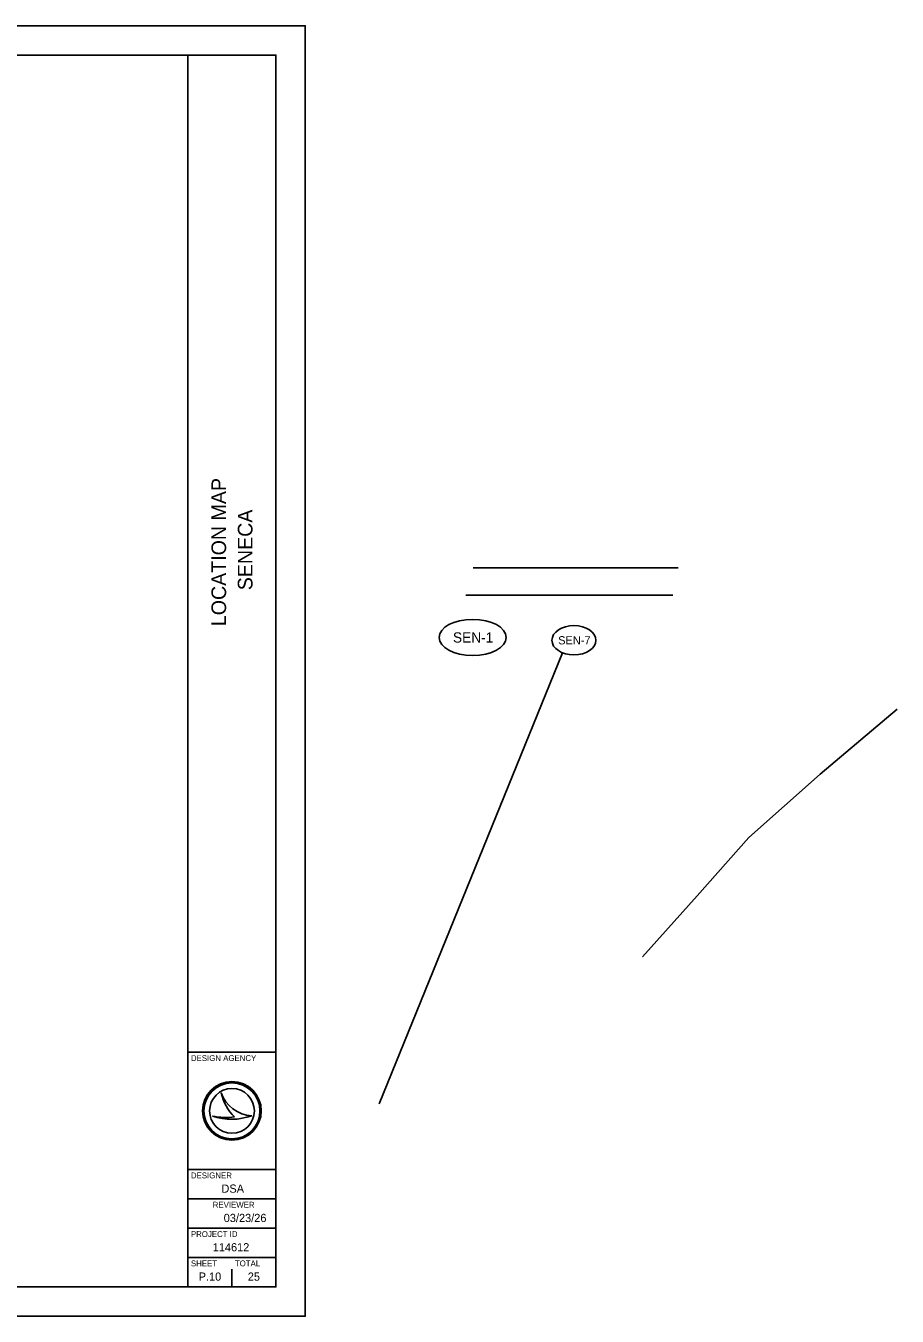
# Model space of a CAD drawing. Extents: x 0 to 882, y 0 to 440.
# Drawn here: x 584.7 to 881.9, y 0 to 440 of the extents above; entities that cross this region are included whole.
import ezdxf

# ---------------------------------------------------------------- set-up
doc = ezdxf.new("R2010")
doc.units = 0
for name, color, linetype in [('RD_P_Fence', 7, 'Continuous'), ('SH_Border', 7, 'Continuous'), ('SH_Cut_Line', 7, 'Continuous'), ('SH_Data', 7, 'Continuous')]:
    doc.layers.add(name, color=color, linetype=linetype)

msp = doc.modelspace()

# ---------------------------------------------------------------- linework, layer by layer
at = {"layer": 'RD_P_Fence'}
for p, q in [((805.35, 245.81), (734.79, 245.81)), ((767.71, 226.2), (705.24, 72.44))]:
    msp.add_line(p, q, dxfattribs=at)
for points in [[(737.28, 255.19), (807.23, 255.19)], [(794.99, 122.57), (813.61, 143.35), (831.26, 163.19), (855.56, 184.87), (881.88, 206.94)]]:
    msp.add_lwpolyline(points, dxfattribs=at)
for centre, major_axis, ratio in [((737.08, 231.44), (11.44, 0), 0.539374), ((771.62, 230.47), (7.5, 0), 0.666667)]:
    msp.add_ellipse(centre, major_axis=major_axis, ratio=ratio, dxfattribs=at)
at = {"layer": 'SH_Border'}
for p, q in [((640, 10), (640, 430)), ((640, 90), (670, 90)), ((640, 50), (670, 50)), ((640, 40), (670, 40)), ((640, 30), (670, 30)), ((640, 20), (670, 20))]:
    msp.add_line(p, q, dxfattribs=at)
msp.add_lwpolyline([(30, 430), (670, 430), (670, 10), (30, 10)], close=True, dxfattribs=at)
at = {"layer": 'SH_Cut_Line'}
msp.add_lwpolyline([(0, 0), (680, 0), (680, 440), (0, 440)], close=True, dxfattribs=at)
at = {"layer": 'SH_Data'}
for p, q in [((651.35, 76.19), (651.35, 76.19)), ((648.34, 68.19), (648.34, 68.19)), ((655, 70), (655, 70)), ((661.75, 68.37), (661.75, 68.37)), ((647.5, 13.5), (647.5, 13.5)), ((655, 10), (655, 16))]:
    msp.add_line(p, q, dxfattribs=at)
for radius in [10, 9.54, 9.54, 7.64]:
    msp.add_circle((655, 70), radius, dxfattribs=at)
for centre, radius, start, end in [((662.32, 79.95), 11.6, 198.9257, 198.9319), ((666.93, 79.4), 15.91, 191.6379, 191.6421), ((662.32, 79.95), 11.6, 198.9319, 267.1657), ((666.93, 79.4), 15.91, 191.6421, 226.0947), ((654.79, 87.4), 20.26, 251.4576, 290.0832), ((652.96, 93.09), 25.32, 259.4964, 259.4995), ((654.79, 87.4), 20.26, 251.4527, 251.4576), ((652.96, 93.09), 25.32, 259.4995, 276.6672)]:
    msp.add_arc(centre, radius, start, end, dxfattribs=at)

# ---------------------------------------------------------------- texts
at = {"layer": 'RD_P_Fence'}
for s, height, p in [('SEN-1', 3.5, (730.36, 229.69)), ('SEN-7', 2.8, (766.26, 229.07))]:
    msp.add_text(s, height=height, dxfattribs=at).set_placement(p)
at = {"layer": 'SH_Data'}
for s, p in [('LOCATION MAP', (653, 235.29)), ('SENECA', (662, 247.54))]:
    msp.add_text(s, height=5, rotation=90, dxfattribs=at).set_placement(p)
for s, height, p in [('DESIGN AGENCY', 2, (641, 87)), ('DESIGNER', 2, (641, 47)), ('DSA', 2.8, (651.41, 42.1)), ('REVIEWER', 2, (648.44, 37)), ('03/23/26', 2.8, (652.18, 32.1)), ('PROJECT ID', 2, (641, 27)), ('114612', 2.8, (648.42, 22.1)), ('SHEET', 2, (641, 17)), ('TOTAL', 2, (656, 17)), ('P.10', 2.8, (643.64, 12.1)), ('25', 2.8, (660.39, 12.1))]:
    msp.add_text(s, height=height, dxfattribs=at).set_placement(p)

doc.saveas('drawing.dxf')
